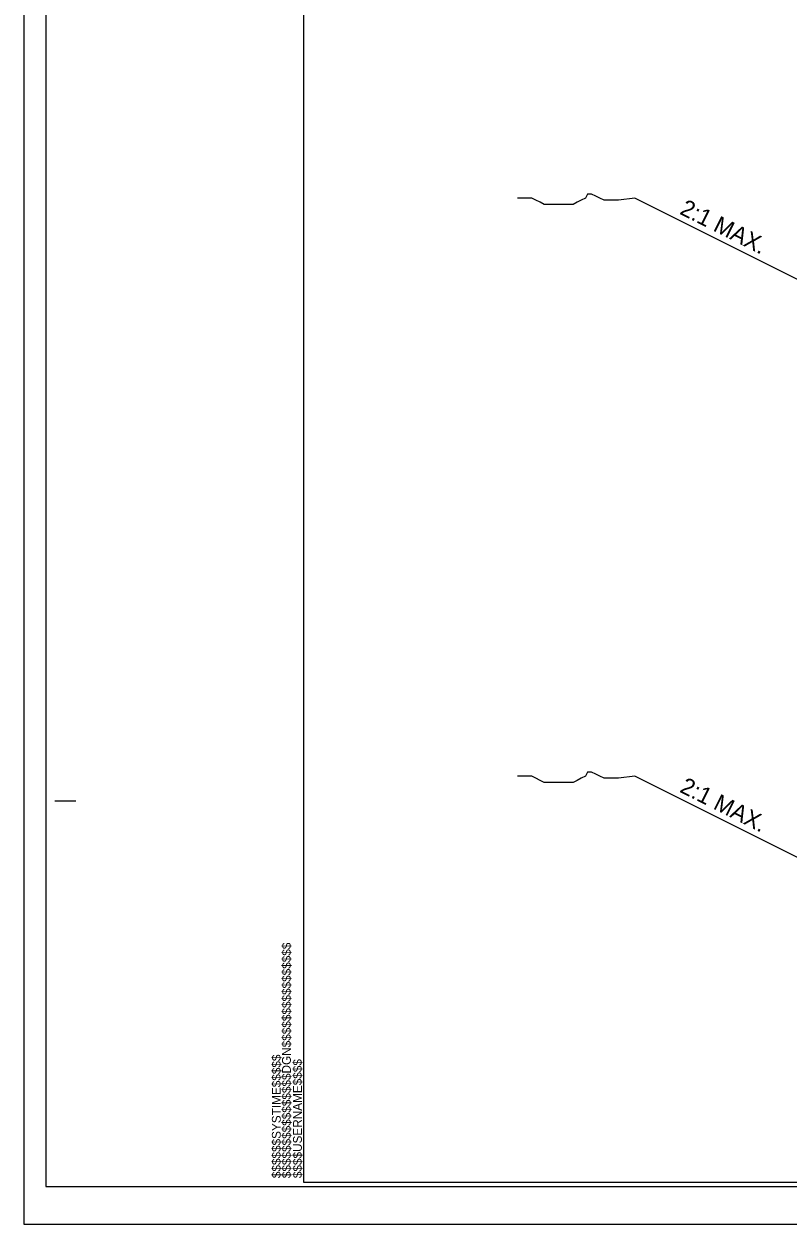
# Model space of a CAD drawing. Extents: x 574216 to 574384, y -52685 to -52551.
# Drawn here: x 574215.6 to 574261.2, y -52685.3 to -52613.6 of the extents above; entities that cross this region are included whole.
import ezdxf

# ---------------------------------------------------------------- set-up
doc = ezdxf.new("R2010")
doc.units = 0
for name, color, linetype in [('Old_Level_1', 7, 'Continuous'), ('Sheet Cutting Line CELL', 7, 'Continuous'), ('Sheet Plot Border Inside CELL', 7, 'Continuous'), ('Sheet Plot Border Outside CELL', 7, 'Continuous'), ('Sheet Typical CELL', 7, 'Continuous')]:
    doc.layers.add(name, color=color, linetype=linetype)

msp = doc.modelspace()

# ---------------------------------------------------------------- linework, layer by layer
at = {"layer": 'Old_Level_1'}
for p, q in [((574262.322, -52629.161), (574252.062, -52624.031)), ((574262.322, -52663.661), (574252.062, -52658.531))]:
    msp.add_line(p, q, dxfattribs=at)
for points in [[(574252.062, -52624.031), (574251.076, -52624.154), (574250.83, -52624.154), (574250.46, -52624.154), (574250.213, -52624.154), (574249.967, -52624.031), (574249.721, -52623.908), (574249.474, -52623.784), (574249.228, -52623.784), (574249.104, -52624.031), (574248.858, -52624.154), (574248.612, -52624.278), (574248.365, -52624.4), (574248.119, -52624.4), (574247.872, -52624.4), (574247.626, -52624.4), (574247.38, -52624.4), (574247.133, -52624.4), (574246.887, -52624.4), (574246.641, -52624.4), (574246.394, -52624.278), (574246.148, -52624.154), (574245.902, -52624.031), (574245.531, -52624.031), (574245.285, -52624.031), (574245.039, -52624.031)], [(574252.062, -52658.531), (574251.076, -52658.654), (574250.83, -52658.654), (574250.46, -52658.654), (574250.213, -52658.654), (574249.967, -52658.531), (574249.721, -52658.408), (574249.474, -52658.284), (574249.228, -52658.284), (574249.104, -52658.531), (574248.858, -52658.654), (574248.612, -52658.778), (574248.365, -52658.9), (574248.119, -52658.9), (574247.872, -52658.9), (574247.626, -52658.9), (574247.38, -52658.9), (574247.133, -52658.9), (574246.887, -52658.9), (574246.641, -52658.9), (574246.394, -52658.778), (574246.148, -52658.654), (574245.902, -52658.531), (574245.531, -52658.531), (574245.285, -52658.531), (574245.039, -52658.531)]]:
    msp.add_lwpolyline(points, dxfattribs=at)
at = {"layer": 'Sheet Cutting Line CELL'}
for p, q in [((574215.577, -52575.254), (574215.577, -52685.254)), ((574215.577, -52685.254), (574383.977, -52685.254))]:
    msp.add_line(p, q, dxfattribs=at)
at = {"layer": 'Sheet Plot Border Inside CELL'}
msp.add_lwpolyline([(574383.527, -52577.499), (574216.877, -52577.499), (574216.877, -52683.009), (574383.527, -52683.009)], close=True, dxfattribs=at)
at = {"layer": 'Sheet Plot Border Outside CELL'}
msp.add_lwpolyline([(574383.977, -52575.254), (574215.577, -52575.254), (574215.577, -52685.254), (574383.977, -52685.254)], close=True, dxfattribs=at)
at = {"layer": 'Sheet Typical CELL'}
for p, q in [((574217.427, -52660.004), (574218.677, -52660.004)), ((574232.277, -52682.754), (574232.277, -52682.754)), ((574232.277, -52682.754), (574232.277, -52682.754)), ((574232.277, -52682.754), (574232.277, -52682.754)), ((574232.277, -52682.754), (574232.277, -52682.754)), ((574232.277, -52682.754), (574232.277, -52682.754)), ((574232.277, -52682.754), (574232.277, -52682.754))]:
    msp.add_line(p, q, dxfattribs=at)
msp.add_lwpolyline([(574382.277, -52577.754), (574232.277, -52577.754), (574232.277, -52682.754), (574382.277, -52682.754)], close=True, dxfattribs=at)
msp.add_lwpolyline([(574236.027, -52682.754), (574236.027, -52682.754)], dxfattribs=at)

# ---------------------------------------------------------------- texts
at = {"layer": 'Old_Level_1'}
for p in [(574254.679, -52624.949), (574254.679, -52659.449)]:
    msp.add_text('2:1 MAX.', height=1, rotation=333.43495, dxfattribs=at).set_placement(p)
at = {"layer": 'Sheet Typical CELL'}
for s, p in [('$$$$$$$$$$$$$$$$DGN$$$$$$$$$$$$$$$$', (574231.512, -52682.517)), ('$$$$$$SYSTIME$$$$$', (574230.907, -52682.517)), ('$$$$USERNAME$$$$', (574232.169, -52682.516))]:
    msp.add_text(s, height=0.525, rotation=90, dxfattribs=at).set_placement(p)

doc.saveas('drawing.dxf')
